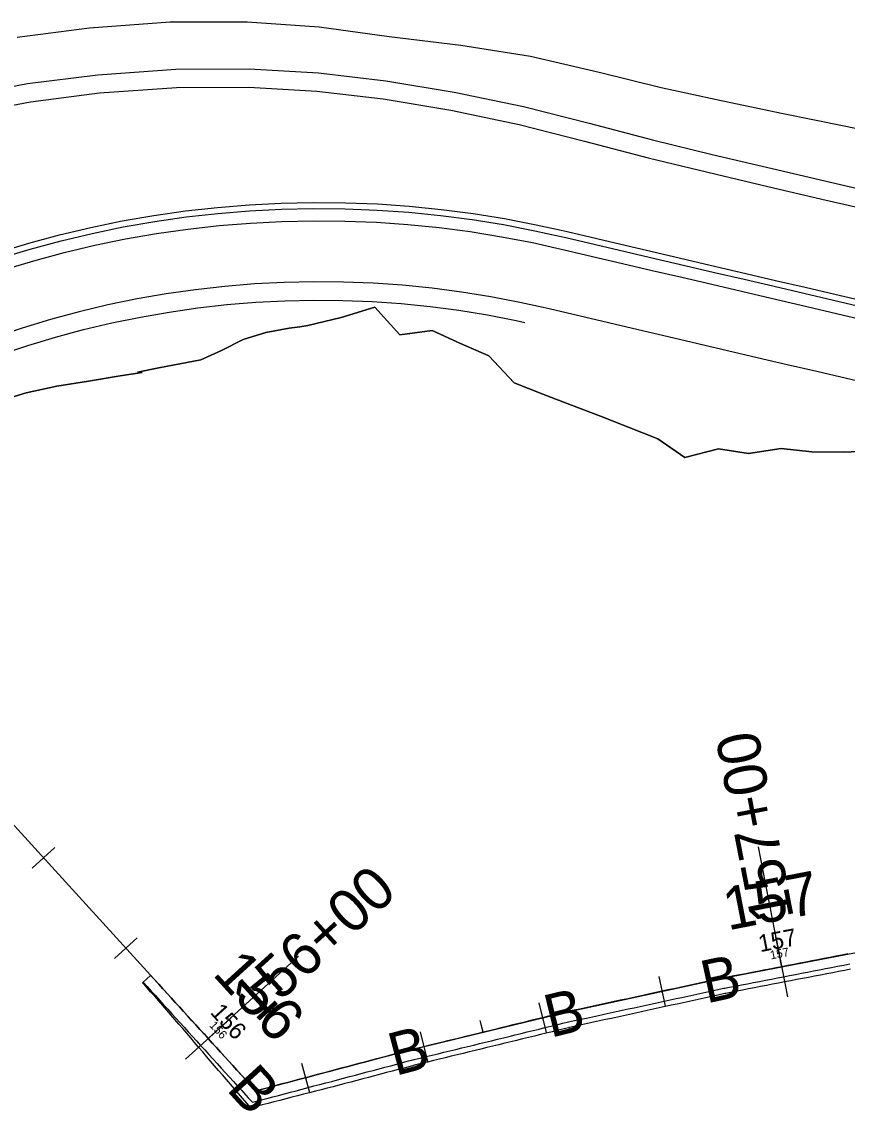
# Model space of a CAD drawing. Extents: x 1823824 to 1861612, y 706975 to 726130.
# Drawn here: x 1825529.3 to 1825664.3, y 715493.1 to 715671.4 of the extents above; entities that cross this region are included whole.
import ezdxf

# ---------------------------------------------------------------- set-up
doc = ezdxf.new("R2010")
doc.units = 0
for name, color, linetype in [('DR_X_Flood_Boundary', 7, 'Continuous'), ('GE_X_CL_10', 7, 'Continuous'), ('GE_X_CL_100', 7, 'Continuous'), ('GE_X_CL_20', 7, 'Continuous'), ('GE_X_CL_200', 7, 'Continuous'), ('GE_X_CL_50', 7, 'Continuous'), ('SC_Scratch1', 7, 'Continuous'), ('SC_Scratch3', 7, 'Continuous'), ('SC_Scratch5', 7, 'Continuous'), ('SC_Scratch6', 7, 'Continuous')]:
    doc.layers.add(name, color=color, linetype=linetype)

msp = doc.modelspace()

# ---------------------------------------------------------------- linework, layer by layer
at = {"layer": 'DR_X_Flood_Boundary'}
for p, q in [((1825513.59, 715555.77), (1825567.61, 715496.42)), ((1825643.98, 715514.87), (1825669.7, 715519.85)), ((1825618.38, 715509.33), (1825643.98, 715514.87)), ((1825592.93, 715503.13), (1825618.38, 715509.33)), ((1825567.61, 715496.42), (1825592.93, 715503.13))]:
    msp.add_line(p, q, dxfattribs=at)
at = {"layer": 'GE_X_CL_10'}
for p, q in [((1825653.63, 715516.74), (1825653.44, 715517.73)), ((1825559.81, 715504.99), (1825560.55, 715505.66)), ((1825604.8, 715506.02), (1825604.57, 715506.99))]:
    msp.add_line(p, q, dxfattribs=at)
at = {"layer": 'GE_X_CL_100'}
for p, q in [((1825653.63, 715516.74), (1825651.73, 715526.56)), ((1825559.81, 715504.99), (1825567.2, 715511.72))]:
    msp.add_line(p, q, dxfattribs=at)
at = {"layer": 'GE_X_CL_20'}
for p, q in [((1825653.63, 715516.74), (1825653.25, 715518.71)), ((1825604.8, 715506.02), (1825604.33, 715507.96)), ((1825559.81, 715504.99), (1825561.29, 715506.33))]:
    msp.add_line(p, q, dxfattribs=at)
at = {"layer": 'GE_X_CL_200'}
for p, q in [((1825653.63, 715516.74), (1825649.83, 715536.38)), ((1825559.81, 715504.99), (1825574.6, 715518.45))]:
    msp.add_line(p, q, dxfattribs=at)
at = {"layer": 'GE_X_CL_50'}
for p, q in [((1825653.63, 715516.74), (1825652.68, 715521.65)), ((1825559.81, 715504.99), (1825563.51, 715508.35))]:
    msp.add_line(p, q, dxfattribs=at)
at = {"layer": 'SC_Scratch1'}
msp.add_line((1825662.12, 715625.82), (1825662.12, 715625.82), dxfattribs=at)
for points in [[(1825528.59, 715668.86), (1825540.4, 715670.37), (1825553.63, 715671.36), (1825566.19, 715671.39), (1825577.99, 715670.57), (1825589.44, 715668.99), (1825601.17, 715667.57), (1825612.54, 715665.75), (1825623.77, 715663.16), (1825633.92, 715660.63), (1825643.99, 715658.43), (1825653.89, 715656.38), (1825663.57, 715654.39), (1825673.68, 715652.35), (1825682.56, 715650.87), (1825693.93, 715649.06), (1825704.45, 715647.73), (1825716.32, 715645.7), (1825727.12, 715643.32), (1825738.2, 715640.21), (1825749.67, 715636.1), (1825759.12, 715631.42), (1825768.57, 715626.56), (1825771.61, 715624.85)], [(1825520.84, 715659.46), (1825530.29, 715661.26), (1825541.76, 715662.72), (1825554.55, 715663.63), (1825566.54, 715663.68), (1825577.88, 715663.03), (1825588.87, 715661.73), (1825600.05, 715659.86), (1825611.38, 715657.51), (1825622.12, 715654.77), (1825632.51, 715652.05), (1825642.26, 715649.67), (1825652.07, 715647.37), (1825661.6, 715645.14), (1825671.44, 715642.87)], [(1825521.48, 715656.52), (1825530.76, 715658.3), (1825542.06, 715659.74), (1825554.66, 715660.63), (1825566.46, 715660.68), (1825577.61, 715660.04), (1825588.45, 715658.75), (1825599.5, 715656.91), (1825610.7, 715654.58), (1825621.37, 715651.87), (1825631.77, 715649.14), (1825641.57, 715646.75), (1825651.39, 715644.45), (1825660.92, 715642.22), (1825670.8, 715639.94)], [(1825525.44, 715633.65), (1825530.46, 715635.17), (1825535.52, 715636.53), (1825540.62, 715637.74), (1825545.75, 715638.79), (1825550.92, 715639.69), (1825556.11, 715640.44), (1825561.32, 715641.02), (1825566.54, 715641.45), (1825571.78, 715641.72), (1825577.02, 715641.83), (1825582.26, 715641.78), (1825587.5, 715641.57), (1825592.72, 715641.21), (1825597.94, 715640.69), (1825603.14, 715640.01), (1825608.31, 715639.17), (1825613.46, 715638.18), (1825617.55, 715637.27), (1825618.53, 715637.05), (1825623.4, 715635.91), (1825628.26, 715634.77), (1825633.13, 715633.63), (1825638, 715632.49), (1825642.87, 715631.35), (1825647.74, 715630.21), (1825652.61, 715629.07), (1825657.48, 715627.93), (1825662.34, 715626.79)], [(1825525.74, 715632.7), (1825530.73, 715634.2), (1825535.76, 715635.56), (1825540.83, 715636.76), (1825545.94, 715637.81), (1825551.07, 715638.7), (1825556.23, 715639.44), (1825561.41, 715640.02), (1825566.6, 715640.45), (1825571.81, 715640.72), (1825577.02, 715640.83), (1825582.23, 715640.78), (1825587.44, 715640.58), (1825592.64, 715640.21), (1825597.82, 715639.69), (1825602.99, 715639.02), (1825608.13, 715638.19), (1825613.25, 715637.2), (1825617.31, 715636.3), (1825618.3, 715636.07), (1825623.17, 715634.93), (1825628.04, 715633.79), (1825632.9, 715632.65), (1825637.77, 715631.51), (1825642.64, 715630.37), (1825647.51, 715629.24), (1825652.38, 715628.1), (1825657.25, 715626.96), (1825662.12, 715625.82)], [(1825526.35, 715630.79), (1825531.28, 715632.28), (1825536.26, 715633.62), (1825541.27, 715634.81), (1825546.31, 715635.85), (1825551.39, 715636.73), (1825556.49, 715637.46), (1825561.61, 715638.03), (1825566.74, 715638.45), (1825571.88, 715638.72), (1825577.03, 715638.83), (1825582.19, 715638.78), (1825587.33, 715638.58), (1825592.47, 715638.22), (1825597.6, 715637.71), (1825602.7, 715637.04), (1825607.79, 715636.22), (1825612.85, 715635.24), (1825616.87, 715634.35), (1825617.84, 715634.12), (1825622.71, 715632.99), (1825627.58, 715631.85), (1825632.45, 715630.71), (1825637.32, 715629.57), (1825642.19, 715628.43), (1825647.05, 715627.29), (1825651.92, 715626.15), (1825656.79, 715625.01), (1825661.66, 715623.87)], [(1825669.12, 715611.86), (1825664.25, 715613), (1825659.38, 715614.14), (1825654.51, 715615.27), (1825649.64, 715616.41), (1825644.78, 715617.55), (1825639.91, 715618.69), (1825635.04, 715619.83), (1825630.17, 715620.97), (1825625.3, 715622.11), (1825620.43, 715623.25), (1825615.57, 715624.39), (1825614.59, 715624.61), (1825610.8, 715625.45), (1825606.04, 715626.37), (1825601.26, 715627.14), (1825596.45, 715627.77), (1825591.62, 715628.26), (1825586.79, 715628.59), (1825581.94, 715628.78), (1825577.09, 715628.83), (1825572.25, 715628.73), (1825567.4, 715628.48), (1825562.57, 715628.08), (1825557.75, 715627.54), (1825552.95, 715626.85), (1825548.18, 715626.02), (1825543.43, 715625.05), (1825538.71, 715623.93), (1825534.03, 715622.67), (1825529.39, 715621.27), (1825524.79, 715619.72)], [(1825662.34, 715626.79), (1825667.21, 715625.65)], [(1825525.79, 715616.89), (1825530.3, 715618.41), (1825534.85, 715619.78), (1825539.45, 715621.02), (1825544.08, 715622.12), (1825548.74, 715623.07), (1825553.42, 715623.89), (1825558.13, 715624.56), (1825562.86, 715625.1), (1825567.6, 715625.48), (1825572.36, 715625.73), (1825577.11, 715625.83), (1825581.87, 715625.79), (1825586.62, 715625.6), (1825591.37, 715625.27), (1825596.11, 715624.79), (1825600.82, 715624.18), (1825605.52, 715623.42), (1825610.19, 715622.52), (1825611.61, 715622.2)], [(1825662.12, 715625.82), (1825666.98, 715624.68)], [(1825525.2, 715609.19), (1825530.06, 715610.64), (1825535.09, 715611.76), (1825540.26, 715612.6), (1825545.43, 715613.43), (1825549, 715614.01), (1825548.25, 715614.05), (1825551.75, 715614.73), (1825555.2, 715615.4), (1825558.63, 715616.07), (1825562, 715617.6), (1825565.52, 715619.37), (1825569.25, 715620.54), (1825573.09, 715621.23), (1825574.83, 715621.49), (1825576.11, 715621.71), (1825581.55, 715623.01), (1825587.07, 715624.66), (1825591.15, 715620.16), (1825596.45, 715620.85), (1825601.08, 715618.73), (1825605.75, 715616.73), (1825609.86, 715612.32), (1825614.55, 715610.42), (1825619.26, 715608.63), (1825623.97, 715606.82), (1825628.68, 715604.99), (1825633.39, 715603.16), (1825637.81, 715600.1), (1825643.27, 715601.51), (1825648.22, 715600.71), (1825653.55, 715601.54), (1825658.56, 715601), (1825663.69, 715600.98), (1825668.87, 715601.18)], [(1825668.87, 715601.18), (1825663.69, 715600.98), (1825658.56, 715601), (1825653.55, 715601.54), (1825648.22, 715600.71), (1825643.27, 715601.51), (1825637.81, 715600.1), (1825633.39, 715603.16), (1825628.68, 715604.99), (1825623.97, 715606.82), (1825619.26, 715608.63), (1825614.55, 715610.42), (1825609.86, 715612.32), (1825605.75, 715616.73), (1825601.08, 715618.73), (1825596.45, 715620.85), (1825591.15, 715620.16), (1825587.07, 715624.66), (1825581.55, 715623.01), (1825576.11, 715621.71), (1825574.83, 715621.49), (1825573.09, 715621.23), (1825569.25, 715620.54), (1825565.52, 715619.37), (1825562, 715617.6), (1825558.63, 715616.07), (1825555.2, 715615.4), (1825551.75, 715614.73), (1825548.25, 715614.05), (1825549, 715614.01), (1825545.43, 715613.43), (1825540.26, 715612.6), (1825535.09, 715611.76), (1825530.06, 715610.64), (1825525.2, 715609.19)], [(1825661.66, 715623.87), (1825666.53, 715622.73)]]:
    msp.add_lwpolyline(points, dxfattribs=at)
at = {"layer": 'SC_Scratch3'}
for points in [[(1825664.43, 715518.84), (1825663.45, 715518.65), (1825662.47, 715518.46), (1825661.48, 715518.27), (1825660.5, 715518.08), (1825659.52, 715517.89), (1825658.54, 715517.7), (1825657.56, 715517.51), (1825656.58, 715517.32), (1825655.59, 715517.13), (1825654.61, 715516.94), (1825653.63, 715516.75), (1825652.65, 715516.56), (1825651.67, 715516.37), (1825650.68, 715516.18), (1825649.7, 715515.99), (1825648.72, 715515.8), (1825647.74, 715515.61), (1825646.76, 715515.42), (1825645.78, 715515.23), (1825644.79, 715515.04), (1825643.98, 715514.88), (1825643.81, 715514.85), (1825642.84, 715514.64), (1825641.86, 715514.43), (1825640.88, 715514.21), (1825639.9, 715514), (1825638.93, 715513.79), (1825637.95, 715513.58), (1825636.97, 715513.37), (1825635.99, 715513.15), (1825635.02, 715512.94), (1825634.04, 715512.73), (1825633.06, 715512.52), (1825632.08, 715512.31), (1825631.11, 715512.1), (1825630.13, 715511.88), (1825629.15, 715511.67), (1825628.18, 715511.46), (1825627.2, 715511.25), (1825626.22, 715511.04), (1825625.24, 715510.83), (1825624.27, 715510.61), (1825623.29, 715510.4), (1825622.31, 715510.19), (1825621.33, 715509.98), (1825620.36, 715509.77), (1825619.38, 715509.56), (1825618.4, 715509.34), (1825618.38, 715509.34), (1825617.43, 715509.11), (1825616.46, 715508.87), (1825615.49, 715508.63), (1825614.52, 715508.4)], [(1825636.97, 715513.38), (1825637.95, 715513.59), (1825638.92, 715513.8), (1825639.9, 715514.01), (1825640.88, 715514.22), (1825641.86, 715514.43), (1825642.83, 715514.65), (1825643.81, 715514.86), (1825643.98, 715514.89), (1825644.79, 715515.05), (1825645.77, 715515.24), (1825646.76, 715515.43), (1825647.74, 715515.62), (1825648.72, 715515.81), (1825649.7, 715516), (1825650.68, 715516.19), (1825651.66, 715516.38), (1825652.65, 715516.57), (1825653.63, 715516.76), (1825654.61, 715516.95), (1825655.59, 715517.14), (1825656.57, 715517.33), (1825657.56, 715517.52), (1825658.54, 715517.71), (1825659.52, 715517.9), (1825660.5, 715518.09), (1825661.48, 715518.28), (1825662.46, 715518.47), (1825663.45, 715518.66), (1825664.43, 715518.85)], [(1825664.91, 715516.34), (1825663.93, 715516.15), (1825662.95, 715515.96), (1825661.97, 715515.77), (1825660.99, 715515.58), (1825660, 715515.39), (1825659.02, 715515.2), (1825658.04, 715515.01), (1825657.06, 715514.82), (1825656.08, 715514.63), (1825655.1, 715514.44), (1825654.11, 715514.25), (1825653.13, 715514.06), (1825652.15, 715513.87), (1825651.17, 715513.68), (1825650.19, 715513.49), (1825649.21, 715513.3), (1825648.22, 715513.11), (1825647.24, 715512.91), (1825646.26, 715512.72), (1825645.28, 715512.53), (1825644.52, 715512.38), (1825644.35, 715512.35), (1825643.38, 715512.14), (1825642.4, 715511.92), (1825641.42, 715511.71), (1825640.45, 715511.5), (1825639.47, 715511.28), (1825638.49, 715511.07), (1825637.51, 715510.86), (1825636.54, 715510.64), (1825635.56, 715510.43), (1825634.58, 715510.22), (1825633.61, 715510.01), (1825632.63, 715509.79), (1825631.65, 715509.58), (1825630.68, 715509.37), (1825629.7, 715509.15), (1825628.72, 715508.94), (1825627.74, 715508.73), (1825626.77, 715508.51), (1825625.79, 715508.3), (1825624.81, 715508.09), (1825623.84, 715507.87), (1825622.86, 715507.66), (1825621.88, 715507.45), (1825620.91, 715507.23), (1825619.93, 715507.02), (1825618.95, 715506.81), (1825618.99, 715506.82), (1825618.04, 715506.59), (1825617.07, 715506.35), (1825616.1, 715506.11), (1825615.13, 715505.87)], [(1825637.32, 715511.73), (1825638.3, 715511.95), (1825639.28, 715512.16), (1825640.26, 715512.37), (1825641.23, 715512.58), (1825642.21, 715512.79), (1825643.19, 715513), (1825644.17, 715513.22), (1825644.33, 715513.25), (1825645.11, 715513.4), (1825646.09, 715513.59), (1825647.08, 715513.78), (1825648.06, 715513.97), (1825649.04, 715514.16), (1825650.02, 715514.35), (1825651, 715514.54), (1825651.98, 715514.73), (1825652.97, 715514.92), (1825653.95, 715515.11), (1825654.93, 715515.3), (1825655.91, 715515.49), (1825656.89, 715515.68), (1825657.87, 715515.87), (1825658.86, 715516.06), (1825659.84, 715516.25), (1825660.82, 715516.44), (1825661.8, 715516.63), (1825662.78, 715516.82), (1825663.77, 715517.01), (1825664.75, 715517.2)], [(1825550.41, 715515.33), (1825550.41, 715515.33), (1825549.18, 715514.2), (1825549.09, 715514.12)], [(1825550.41, 715515.33), (1825551.07, 715514.61), (1825551.74, 715513.87), (1825552.41, 715513.13), (1825553.09, 715512.39), (1825553.76, 715511.65), (1825554.43, 715510.91), (1825555.11, 715510.17), (1825555.78, 715509.43), (1825556.45, 715508.7), (1825557.13, 715507.96), (1825557.8, 715507.22), (1825558.47, 715506.48), (1825559.15, 715505.74), (1825559.82, 715505), (1825560.49, 715504.26), (1825561.17, 715503.52), (1825561.84, 715502.78), (1825562.51, 715502.04), (1825563.19, 715501.3), (1825563.86, 715500.56), (1825564.53, 715499.82), (1825565.21, 715499.08), (1825565.88, 715498.34), (1825566.55, 715497.6), (1825567.23, 715496.87), (1825567.62, 715496.43), (1825568, 715496.54), (1825568.97, 715496.8), (1825569.94, 715497.06), (1825570.9, 715497.31), (1825571.87, 715497.57), (1825572.84, 715497.82), (1825573.8, 715498.08), (1825574.77, 715498.34), (1825575.74, 715498.59), (1825576.7, 715498.85), (1825577.67, 715499.1), (1825578.64, 715499.36), (1825579.6, 715499.62), (1825580.57, 715499.87), (1825581.54, 715500.13), (1825582.5, 715500.39), (1825583.47, 715500.64), (1825584.44, 715500.9), (1825585.4, 715501.15), (1825586.37, 715501.41), (1825587.34, 715501.66), (1825588.3, 715501.92), (1825589.27, 715502.18), (1825590.24, 715502.43), (1825591.2, 715502.69), (1825592.17, 715502.94), (1825592.92, 715503.14), (1825593.14, 715503.2), (1825594.11, 715503.43), (1825595.08, 715503.67), (1825596.05, 715503.91), (1825597.03, 715504.14), (1825598, 715504.38), (1825598.97, 715504.62), (1825599.94, 715504.85), (1825600.91, 715505.09), (1825601.88, 715505.33), (1825602.85, 715505.56), (1825603.83, 715505.8), (1825604.8, 715506.04), (1825605.77, 715506.28), (1825606.74, 715506.51), (1825607.71, 715506.75), (1825608.68, 715506.99), (1825609.66, 715507.22), (1825610.63, 715507.46), (1825611.6, 715507.7), (1825612.57, 715507.93), (1825613.54, 715508.17), (1825614.51, 715508.41), (1825615.48, 715508.64), (1825616.46, 715508.88), (1825617.43, 715509.12), (1825618.37, 715509.35), (1825618.4, 715509.35), (1825619.38, 715509.57), (1825620.35, 715509.78), (1825621.33, 715509.99), (1825622.31, 715510.2), (1825623.29, 715510.41), (1825624.26, 715510.62), (1825625.24, 715510.84), (1825626.22, 715511.05), (1825627.2, 715511.26), (1825628.17, 715511.47), (1825629.15, 715511.68), (1825630.13, 715511.89), (1825631.11, 715512.11), (1825632.08, 715512.32), (1825633.06, 715512.53), (1825634.04, 715512.74), (1825635.01, 715512.95), (1825635.99, 715513.16), (1825636.97, 715513.38)], [(1825614.52, 715508.4), (1825613.54, 715508.16), (1825612.57, 715507.92), (1825611.6, 715507.69), (1825610.63, 715507.45), (1825609.66, 715507.21), (1825608.69, 715506.98), (1825607.71, 715506.74), (1825606.74, 715506.5), (1825605.77, 715506.27), (1825604.8, 715506.03), (1825603.83, 715505.79), (1825602.86, 715505.56), (1825601.89, 715505.32), (1825600.91, 715505.08), (1825599.94, 715504.85), (1825598.97, 715504.61), (1825598, 715504.37), (1825597.03, 715504.13), (1825596.06, 715503.9), (1825595.08, 715503.66), (1825594.11, 715503.42), (1825593.14, 715503.19), (1825592.93, 715503.14), (1825592.17, 715502.94), (1825591.21, 715502.68), (1825590.24, 715502.42), (1825589.27, 715502.17), (1825588.31, 715501.91), (1825587.34, 715501.66), (1825586.37, 715501.4), (1825585.41, 715501.14), (1825584.44, 715500.89), (1825583.47, 715500.63), (1825582.51, 715500.38), (1825581.54, 715500.12), (1825580.57, 715499.86), (1825579.61, 715499.61), (1825578.64, 715499.35), (1825577.67, 715499.1), (1825576.71, 715498.84), (1825575.74, 715498.58), (1825574.77, 715498.33), (1825573.81, 715498.07), (1825572.84, 715497.82), (1825571.87, 715497.56), (1825570.91, 715497.31), (1825569.94, 715497.05), (1825568.97, 715496.79), (1825568.01, 715496.54), (1825567.61, 715496.43), (1825567.22, 715496.86), (1825566.55, 715497.6), (1825565.87, 715498.34), (1825565.2, 715499.08), (1825564.53, 715499.82), (1825563.86, 715500.56), (1825563.18, 715501.3), (1825562.51, 715502.04), (1825561.84, 715502.78), (1825561.16, 715503.52), (1825560.49, 715504.26), (1825559.82, 715505), (1825559.14, 715505.73), (1825558.47, 715506.47), (1825557.8, 715507.21), (1825557.12, 715507.95), (1825556.45, 715508.69), (1825555.78, 715509.43), (1825555.11, 715510.17), (1825554.43, 715510.91), (1825553.76, 715511.65), (1825553.09, 715512.39), (1825552.41, 715513.13), (1825551.74, 715513.87), (1825551.07, 715514.61), (1825550.41, 715515.33)], [(1825615.13, 715505.87), (1825614.16, 715505.64), (1825613.19, 715505.4), (1825612.22, 715505.16), (1825611.24, 715504.93), (1825610.27, 715504.69), (1825609.3, 715504.46), (1825608.33, 715504.22), (1825607.36, 715503.98), (1825606.39, 715503.74), (1825605.41, 715503.51), (1825604.44, 715503.27), (1825603.47, 715503.03), (1825602.5, 715502.8), (1825601.53, 715502.56), (1825600.56, 715502.32), (1825599.59, 715502.09), (1825598.61, 715501.85), (1825597.64, 715501.61), (1825596.67, 715501.38), (1825595.7, 715501.14), (1825594.73, 715500.9), (1825593.76, 715500.67), (1825593.59, 715500.63), (1825592.84, 715500.43), (1825591.87, 715500.17), (1825590.9, 715499.91), (1825589.94, 715499.66), (1825588.97, 715499.41), (1825588, 715499.15), (1825587.04, 715498.9), (1825586.07, 715498.64), (1825585.1, 715498.39), (1825584.14, 715498.13), (1825583.17, 715497.88), (1825582.2, 715497.62), (1825581.23, 715497.37), (1825580.27, 715497.11), (1825579.3, 715496.86), (1825578.33, 715496.61), (1825577.36, 715496.36), (1825576.39, 715496.12), (1825575.42, 715495.87), (1825574.45, 715495.62), (1825573.49, 715495.38), (1825572.52, 715495.13), (1825571.55, 715494.88), (1825570.58, 715494.63), (1825569.61, 715494.38), (1825568.64, 715494.14), (1825566.81, 715493.66), (1825565.83, 715494.8), (1825565.45, 715495.24), (1825564.79, 715496), (1825564.14, 715496.76), (1825563.49, 715497.52), (1825562.83, 715498.27), (1825562.18, 715499.03), (1825561.53, 715499.79), (1825560.87, 715500.55), (1825560.22, 715501.31), (1825559.57, 715502.07), (1825558.92, 715502.82), (1825558.26, 715503.58), (1825557.61, 715504.34), (1825556.96, 715505.1), (1825556.31, 715505.86), (1825555.65, 715506.62), (1825555, 715507.37), (1825554.35, 715508.13), (1825553.7, 715508.89), (1825553.04, 715509.65), (1825552.39, 715510.4), (1825551.73, 715511.16), (1825551.07, 715511.91), (1825550.4, 715512.65), (1825549.74, 715513.4), (1825549.09, 715514.12)], [(1825549.18, 715514.2), (1825549.83, 715513.49), (1825550.5, 715512.75), (1825551.18, 715512.01), (1825551.85, 715511.27), (1825552.52, 715510.53), (1825553.2, 715509.79), (1825553.87, 715509.05), (1825554.54, 715508.31), (1825555.22, 715507.57), (1825555.89, 715506.83), (1825556.56, 715506.09), (1825557.24, 715505.35), (1825557.91, 715504.61), (1825558.58, 715503.87), (1825559.25, 715503.13), (1825559.93, 715502.39), (1825560.6, 715501.65), (1825561.27, 715500.91), (1825561.95, 715500.17), (1825562.62, 715499.43), (1825563.29, 715498.69), (1825563.97, 715497.95), (1825564.64, 715497.22), (1825565.31, 715496.48), (1825565.99, 715495.74), (1825566.38, 715495.3), (1825567.06, 715494.56), (1825569.4, 715495.18), (1825570.37, 715495.44), (1825571.33, 715495.69), (1825572.3, 715495.95), (1825573.27, 715496.2), (1825574.23, 715496.46), (1825575.2, 715496.71), (1825576.17, 715496.97), (1825577.13, 715497.23), (1825578.1, 715497.48), (1825579.07, 715497.74), (1825580.03, 715497.99), (1825581, 715498.25), (1825581.97, 715498.51), (1825582.93, 715498.76), (1825583.9, 715499.02), (1825584.87, 715499.27), (1825585.83, 715499.53), (1825586.8, 715499.79), (1825587.77, 715500.04), (1825588.73, 715500.3), (1825589.7, 715500.55), (1825590.67, 715500.81), (1825591.63, 715501.07), (1825592.6, 715501.32), (1825593.35, 715501.52), (1825593.54, 715501.56), (1825594.51, 715501.8), (1825595.48, 715502.04), (1825596.45, 715502.28), (1825597.42, 715502.51), (1825598.39, 715502.75), (1825599.37, 715502.99), (1825600.34, 715503.22), (1825601.31, 715503.46), (1825602.28, 715503.7), (1825603.25, 715503.93), (1825604.22, 715504.17), (1825605.2, 715504.41), (1825606.17, 715504.64), (1825607.14, 715504.88), (1825608.11, 715505.12), (1825609.08, 715505.35), (1825610.05, 715505.59), (1825611.02, 715505.83), (1825612, 715506.07), (1825612.97, 715506.3), (1825613.94, 715506.54), (1825614.91, 715506.78), (1825615.88, 715507.01), (1825616.85, 715507.25), (1825617.83, 715507.49), (1825618.77, 715507.72), (1825618.76, 715507.71), (1825619.73, 715507.92), (1825620.71, 715508.14), (1825621.69, 715508.35), (1825622.66, 715508.56), (1825623.64, 715508.77), (1825624.62, 715508.98), (1825625.6, 715509.19), (1825626.57, 715509.41), (1825627.55, 715509.62), (1825628.53, 715509.83), (1825629.51, 715510.04), (1825630.48, 715510.25), (1825631.46, 715510.46), (1825632.44, 715510.68), (1825633.42, 715510.89), (1825634.39, 715511.1), (1825635.37, 715511.31), (1825636.35, 715511.52), (1825637.32, 715511.73)]]:
    msp.add_lwpolyline(points, dxfattribs=at)
at = {"layer": 'SC_Scratch5'}
for points in [[(1825534.73, 715536.25), (1825531.04, 715532.89)], [(1825652.68, 715521.65), (1825654.58, 715511.83)], [(1825548.2, 715521.46), (1825544.5, 715518.1)], [(1825633.51, 715515.17), (1825634.57, 715510.28)], [(1825613.93, 715510.82), (1825615.11, 715505.96)], [(1825563.51, 715508.35), (1825556.11, 715501.62)], [(1825594.49, 715506.08), (1825595.68, 715501.22)], [(1825575.1, 715500.99), (1825576.38, 715496.16)]]:
    msp.add_lwpolyline(points, dxfattribs=at)

# ---------------------------------------------------------------- texts
at = {"layer": 'GE_X_CL_10'}
for s, rotation, p in [('157', 10.9595, (1825651.87, 715517.93)), ('156', 312.3061, (1825559.92, 715507.09))]:
    msp.add_text(s, height=1.4, rotation=rotation, dxfattribs=at).set_placement(p)
at = {"layer": 'GE_X_CL_20'}
for s, rotation, p in [('157', 10.9595, (1825650.11, 715519.12)), ('156', 312.3061, (1825560.04, 715509.19))]:
    msp.add_text(s, height=2.8, rotation=rotation, dxfattribs=at).set_placement(p)
at = {"layer": 'GE_X_CL_50'}
for s, rotation, p in [('157', 10.9595, (1825644.82, 715522.68)), ('156', 312.3061, (1825560.39, 715515.5))]:
    msp.add_text(s, height=7, rotation=rotation, dxfattribs=at).set_placement(p)
at = {"layer": 'SC_Scratch5'}
for s, rotation, p in [('157+00', 100.9595, (1825655.64, 715524.77)), ('156+00', 42.3061, (1825567.71, 715507.45))]:
    msp.add_text(s, height=7, rotation=rotation, dxfattribs=at).set_placement(p)
at = {"layer": 'SC_Scratch6'}
for rotation, p in [(12.2206, (1825641.3, 715510.71)), (13.7004, (1825615.81, 715505.1)), (14.8283, (1825590.44, 715498.85)), (312.3061, (1825562.66, 715496.65))]:
    msp.add_text('B', height=7, rotation=rotation, dxfattribs=at).set_placement(p)

doc.saveas('drawing.dxf')
